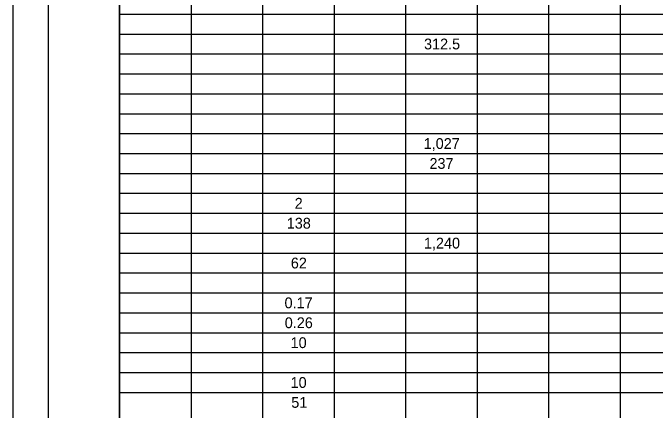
# Model space of a CAD drawing. Extents: x 0 to 34, y 0 to 22.
# Drawn here: x 0 to 9.03, y 10.89 to 16.48 of the extents above; entities that cross this region are included whole.
import ezdxf

# ---------------------------------------------------------------- set-up
doc = ezdxf.new("R2010")
doc.units = 0
for name, color, linetype in [('SH_Border', 7, 'Continuous'), ('SH_Cut_Line', 7, 'Continuous'), ('SH_Text', 7, 'Continuous')]:
    doc.layers.add(name, color=color, linetype=linetype)

msp = doc.modelspace()

# ---------------------------------------------------------------- linework, layer by layer
at = {"layer": 'SH_Border'}
for points in [[(0.5, 21.5), (1.5, 21.5), (1.5, 0.5), (0.5, 0.5)], [(1.5, 21.5), (33.5, 21.5), (33.5, 0.5), (1.5, 0.5)]]:
    msp.add_lwpolyline(points, close=True, dxfattribs=at)
at = {"layer": 'SH_Cut_Line'}
msp.add_lwpolyline([(0, 0), (34, 0), (34, 22), (0, 22)], close=True, dxfattribs=at)
at = {"layer": 'SH_Text'}
for p, q in [((1.5, 21.5), (1.5, 0.5)), ((2.5046, 20.94), (2.5046, 0.5)), ((3.5092, 20.94), (3.5092, 0.5)), ((4.5138, 20.94), (4.5138, 0.5)), ((5.5184, 20.94), (5.5184, 0.5)), ((6.5229, 20.94), (6.5229, 0.5)), ((7.5275, 20.94), (7.5275, 0.5)), ((8.5321, 20.94), (8.5321, 0.5)), ((1.5, 16.46), (32, 16.46)), ((1.5, 16.18), (32, 16.18)), ((1.5, 15.9), (32, 15.9)), ((1.5, 15.62), (32, 15.62)), ((1.5, 15.34), (32, 15.34)), ((1.5, 15.06), (32, 15.06)), ((1.5, 14.78), (32, 14.78)), ((1.5, 14.5), (32, 14.5)), ((1.5, 14.22), (32, 14.22)), ((1.5, 13.94), (32, 13.94)), ((1.5, 13.66), (32, 13.66)), ((1.5, 13.38), (32, 13.38)), ((1.5, 13.1), (32, 13.1)), ((1.5, 12.82), (32, 12.82)), ((1.5, 12.54), (32, 12.54)), ((1.5, 12.26), (32, 12.26)), ((1.5, 11.98), (32, 11.98)), ((1.5, 11.7), (32, 11.7)), ((1.5, 11.42), (32, 11.42)), ((1.5, 11.14), (32, 11.14))]:
    msp.add_line(p, q, dxfattribs=at)

# ---------------------------------------------------------------- texts
for s, height, p in [('312.5', 0.15153, (5.7781, 15.9642)), ('1,027', 0.15153, (5.773, 14.5642)), ('237', 0.15153, (5.8543, 14.2842)), ('2', 0.1515, (3.9606, 13.7242)), ('138', 0.15153, (3.8491, 13.4442)), ('1,240', 0.15153, (5.7764, 13.1642)), ('62', 0.15153, (3.9062, 12.8842)), ('0.17', 0.15153, (3.8179, 12.3242)), ('0.26', 0.15153, (3.8208, 12.0442)), ('10', 0.15153, (3.9029, 11.7642)), ('10', 0.15153, (3.9029, 11.2042)), ('51', 0.15153, (3.9124, 10.9242))]:
    msp.add_text(s, height=height, dxfattribs=at).set_placement(p)

doc.saveas('drawing.dxf')
